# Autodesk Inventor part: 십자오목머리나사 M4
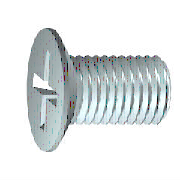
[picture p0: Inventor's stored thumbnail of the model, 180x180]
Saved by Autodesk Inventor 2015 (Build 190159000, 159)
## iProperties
IsCustomPart: 0
Created: 2012-02
Part Number: 십자오목머리나사 M4
Material: 강철, 연강
Description: 십자 오목 머리 나사
Document SubType Name: Modeling
Standard: KS B 1023
Designer: mduedu
Standards Organization: KS
Language: ko-KR
Size Designation: A  M 4 x 12 - H
Categories: <MemberInstance><Categories><Category DisplayName="조임쇠" InternalName="e4da775c-781d-43d5-af7c-5136215cf5a6" Mnemonic="FSTN"><Category DisplayName="볼트" InternalN
Density: 7.86 g/cm^3
Mass: 1.50481 g
Surface Area: 2.78563 cm^2
Volume: 0.191451 cm^3
Appearance: 보라색
Author: mduedu
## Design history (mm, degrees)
body "Solid1"
sketch "스케치1"
  geometry: L1 (2.6, 0)-(12, 0); L2 (12, 0)-(12, 2); L3 (12, 2)-(4.1, 2); L4 (4.1, 2)-(3.671, 1.785); L5 (3.671, 1.785)-(2.7, 1.785); L6 (0, 4.2)-(0, 2.4); L7 (0, 2.4)-(1.801, 1.502); L8 (1.801, 1.502)-(2.6, 0); L9 (-2.4, 0)-(14.4, 0) reference; L10 (0, -0.84)-(0, 5.04) reference; L11 (0, 4.2)-(0.285, 4.2); L12 (0.285, 4.2)-(2.7, 1.785); L13 (4.1, 2)-(2.485, 2)
  constraints: 22 end point, 3 parallel, 3 perpendicular, 2 collinear, 1 horizontal, 1 point on line
  dimensions: "d1" = 7.9 distance of L2.end L3.end (= GEL); "d2" = 4 diameter of L3 L1 (= GD); "d3" = 3.57058 diameter of L5 L1 (= BDM); "d4" = 4.8 diameter of L6.end L1 (= SDM); "d5" = 26.5 deg angle of L7 L1; "d6" = 62 deg angle of L8 L1; "d7" = 2.6 distance from line of L1.start L6 (= INTI); "d8" = 0.42941 horizontal distance of L4.end L3.end (= GAL); "d12" = 8.4 diameter of L11 L1 (= KOD); "d13" = 45 deg angle of L12 L1 (= 0.5 x SEWI); "d15" = 12 distance between parallel lines of L2 L6 (= NLG); "d24" = 2.7 distance from line of L5.end L6 (= KOH)
revolve "본체" stored, may be unused: angle "d16" = 90 deg
sketch "스케치2"
  geometry: L1 (0, 2.4)-(0, 0); L2 (0, 0)-(2.4, 0); L3 (0, 0)-(1.697, 1.697); L4 (0.312, 2.38)-(0.408, 0.734); L5 (2.38, 0.312)-(0.734, 0.408); L6 (0, -5.88)-(0, 5.88) reference; L7 (-5.88, 0)-(5.88, 0) reference; L8 (2.38, -0.312)-(0.734, -0.408); L9 (0.312, -2.38)-(0.408, -0.734); L10 (-0.312, -2.38)-(-0.408, -0.734); L11 (-2.38, -0.312)-(-0.734, -0.408); L12 (-2.38, 0.312)-(-0.734, 0.408); L13 (-0.312, 2.38)-(-0.408, 0.734); A1 r 0.72 centre (0, 0) between (0.72, 0) and (0, 0.72); A2 r 0.84 centre (0, 0) between (0.84, 0) and (0, 0.84); A3 r 2.4 centre (0, 0) between (2.38, 0.312) and (0.312, 2.38); A4 r 2.4 centre (0, 0) between (0.312, 2.38) and (0, 2.4); A5 r 2.4 centre (0, 0) between (2.4, 0) and (2.38, 0.312); A6 r 2.4 centre (0, 0) between (0, -2.4) and (0.312, -2.38); A7 r 2.4 centre (0, 0) between (0.312, -2.38) and (2.38, -0.312); A8 r 2.4 centre (0, 0) between (2.38, -0.312) and (2.4, 0); A9 r 2.4 centre (0, 0) between (0, 2.4) and (-0.312, 2.38); A10 r 2.4 centre (0, 0) between (-0.312, 2.38) and (-2.38, 0.312); A11 r 2.4 centre (0, 0) between (-2.38, 0.312) and (-2.4, 0); A12 r 2.4 centre (0, 0) between (-2.4, 0) and (-2.38, -0.312); A13 r 2.4 centre (0, 0) between (-2.38, -0.312) and (-0.312, -2.38); A14 r 2.4 centre (0, 0) between (-0.312, -2.38) and (0, -2.4); A15 r 0.347 centre (0.755, 0.755) between (0.408, 0.734) and (0.734, 0.408); A16 r 0.347 centre (0.755, -0.755) between (0.734, -0.408) and (0.408, -0.734); A17 r 0.347 centre (-0.755, -0.755) between (-0.408, -0.734) and (-0.734, -0.408); A18 r 0.347 centre (-0.755, 0.755) between (-0.734, 0.408) and (-0.408, 0.734); 3 further points
  constraints: 41 point on circle, 22 end point, 22 symmetric about line, 18 centre point, 11 coincident, 4 point on line, 3 tangent, 2 collinear, 1 perpendicular, 1 vertical, 19 other
  dimensions: "d17" = 1.44 diameter of A1 (= 0.3 x SDM); "d18" = 1.68 diameter of A2 (= 0.35 x SDM); "d19" = 4.8 diameter of A3 (= SDM); "d20" = 45 deg angle of L3 L2; "d21" = 0.3115 distance from line of L4.start L1 (= 0.5 x SBR)
extrude "슬롯" join sketch "스케치2" taper "d22" = 5 deg; stored distance "d79" = 25.4
fillet "모깎기1" dims "d23" = 0.1246 (= 0.2 x SBR)
feature "스레드" dims "d10" = 7.9 (= GEL), "d11" = 0
chamfer "모따기1" distance "d25" = 0.42941 (= -0.5 x SPD + 0.5 x GD); stored, may be unused: second distance "d26" = 0.21471 (= 0.5 x GAL), angle "d88" = 45 deg
workplane "Work Plane2"
other parameters: "NLG" = 12 [user parameter; used in 1 equation term], "GEL" = 7.9 [user parameter; used in 2 equation terms], "GAL" = 0.42941 (= 0.61345 x PTC) [user parameter; used in 3 equation terms], "SPD" = 3.14117 (= NND - 1.2269 x PTC) [user parameter; used in 1 equation term], "KOD" = 8.4 [user parameter; used in 1 equation term], "KOH" = 2.7 [user parameter; used in 1 equation term], "SBR" = 0.623 [user parameter; used in 2 equation terms], "INTI" = 2.6 [user parameter; used in 1 equation term], "SDM" = 4.8 [user parameter; used in 5 equation terms], "GD" = 4 (= NND) [user parameter; used in 2 equation terms], "BDM" = 3.57058 (= NND - GAL) [user parameter; used in 1 equation term], "SEWI" = 90 deg [user parameter; used in 1 equation term], "d9" = 4.8 (= SDM), "d27" = 0, "d91" = 0, "d92" = 0, "GUL" = 0.42941 (= 0.61345 x PTC) [user parameter], "TOA" = 30 deg [user parameter], "EPV" = 4.7 [user parameter], "THREADDIA" = 4 [user parameter; used in 1 equation term], "TPU" = 14.28571 (computed from PTC) [user parameter], "PTC" = 0.7 [user parameter; used in 5 equation terms], "NND" = 4 [user parameter; used in 3 equation terms], "GD1" = 3.14117 (= THREADDIA - 1.2269 x PTC) [user parameter]
